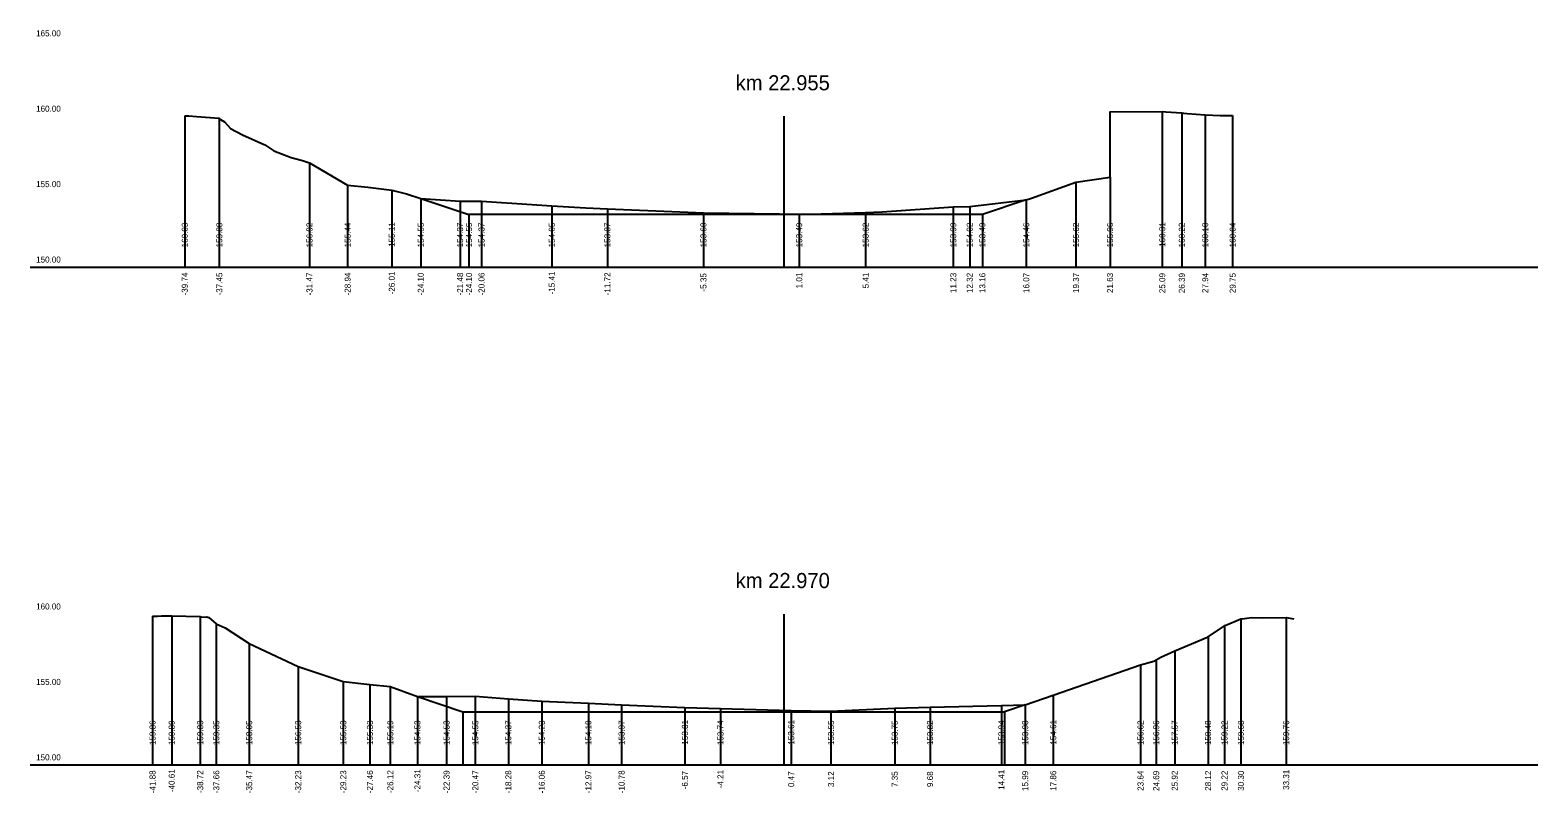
# Model space of a CAD drawing. Extents: x -582678 to -581845, y -1210354 to -1210235.
# Drawn here: x -582385.4 to -582285.4, y -1210306.7 to -1210256.2 of the extents above; entities that cross this region are included whole.
import ezdxf

# ---------------------------------------------------------------- set-up
doc = ezdxf.new("R2010")
doc.units = 0
for name, color, linetype in [('_N_osa', 7, 'Continuous'), ('_N_popis', 7, 'Continuous'), ('_N_tučná', 7, 'Continuous'), ('_S_popis', 7, 'Continuous'), ('_S_popis_oprav!', 7, 'Continuous'), ('_S_tenká', 7, 'Continuous'), ('_S_velmi_tenká', 7, 'Continuous')]:
    doc.layers.add(name, color=color, linetype=linetype)

msp = doc.modelspace()

# ---------------------------------------------------------------- linework, layer by layer
at = {"layer": '_N_osa'}
for p, q in [((-582335.45, -1210261.87), (-582335.45, -1210271.87)), ((-582335.45, -1210294.87), (-582335.45, -1210304.87))]:
    msp.add_line(p, q, dxfattribs=at)
at = {"layer": '_N_popis'}
for p, q in [((-582356.34, -1210268.38), (-582356.34, -1210271.87)), ((-582322.29, -1210268.38), (-582322.29, -1210271.87)), ((-582356.74, -1210301.35), (-582356.74, -1210304.87)), ((-582320.82, -1210301.35), (-582320.82, -1210304.87))]:
    msp.add_line(p, q, dxfattribs=at)
for points in [[(-582359.54, -1210267.32), (-582359.54, -1210271.87), (-582359.54, -1210271.87), (-582359.54, -1210271.87)], [(-582319.38, -1210267.41), (-582319.38, -1210271.87), (-582319.38, -1210271.87), (-582319.38, -1210271.87)]]:
    msp.add_lwpolyline(points, dxfattribs=at)
at = {"layer": '_N_tučná'}
for p, q in [((-582359.54, -1210267.32), (-582356.34, -1210268.38)), ((-582319.38, -1210267.41), (-582322.29, -1210268.38)), ((-582322.29, -1210268.38), (-582356.34, -1210268.38)), ((-582359.76, -1210300.34), (-582356.74, -1210301.35)), ((-582319.45, -1210300.89), (-582320.82, -1210301.35)), ((-582356.74, -1210301.35), (-582320.82, -1210301.35))]:
    msp.add_line(p, q, dxfattribs=at)
at = {"layer": '_S_tenká'}
for p, q in [((-582385.45, -1210271.87), (-582285.45, -1210271.87)), ((-582385.45, -1210304.87), (-582285.45, -1210304.87))]:
    msp.add_line(p, q, dxfattribs=at)
for points in [[(-582375.19, -1210261.84), (-582375.1, -1210261.84), (-582375.03, -1210261.85), (-582374.93, -1210261.84), (-582374.42, -1210261.88), (-582372.9, -1210261.99), (-582372.83, -1210262.08), (-582372.56, -1210262.23), (-582372.16, -1210262.68), (-582371.36, -1210263.1), (-582369.87, -1210263.77), (-582369.28, -1210264.17), (-582368.14, -1210264.6), (-582367.39, -1210264.8), (-582366.92, -1210264.95), (-582364.39, -1210266.43), (-582363.06, -1210266.58), (-582361.46, -1210266.76), (-582360.49, -1210267.01), (-582359.54, -1210267.32), (-582356.93, -1210267.5), (-582355.51, -1210267.49), (-582352.17, -1210267.71), (-582350.85, -1210267.82), (-582348.59, -1210267.94), (-582347.16, -1210268), (-582342.36, -1210268.21), (-582340.79, -1210268.27), (-582335.74, -1210268.35), (-582334.44, -1210268.38), (-582330.03, -1210268.25), (-582328.93, -1210268.2), (-582324.22, -1210267.88), (-582323.13, -1210267.85), (-582319.38, -1210267.41), (-582319.02, -1210267.29), (-582316.08, -1210266.25), (-582313.82, -1210265.91), (-582313.82, -1210261.58), (-582310.36, -1210261.56), (-582310.13, -1210261.57), (-582309.06, -1210261.65), (-582308.94, -1210261.66), (-582308.93, -1210261.66), (-582308.71, -1210261.68), (-582307.51, -1210261.77), (-582306.52, -1210261.82), (-582305.69, -1210261.83)], [(-582377.33, -1210295.01), (-582376.99, -1210295.01), (-582376.73, -1210295), (-582376.06, -1210294.98), (-582374.17, -1210295.04), (-582374.11, -1210295.05), (-582373.81, -1210295.08), (-582373.73, -1210295.06), (-582373.59, -1210295.09), (-582373.1, -1210295.52), (-582372.52, -1210295.78), (-582370.92, -1210296.82), (-582367.67, -1210298.34), (-582364.68, -1210299.34), (-582362.91, -1210299.54), (-582361.56, -1210299.68), (-582359.76, -1210300.34), (-582357.83, -1210300.33), (-582355.92, -1210300.32), (-582353.73, -1210300.5), (-582351.51, -1210300.64), (-582348.42, -1210300.77), (-582346.22, -1210300.9), (-582342.02, -1210301.06), (-582339.66, -1210301.13), (-582334.97, -1210301.26), (-582332.33, -1210301.32), (-582328.1, -1210301.12), (-582325.76, -1210301.05), (-582321.03, -1210300.93), (-582319.45, -1210300.89), (-582317.59, -1210300.25), (-582311.8, -1210298.24), (-582310.91, -1210298), (-582310.76, -1210297.91), (-582310.45, -1210297.72), (-582309.53, -1210297.3), (-582307.32, -1210296.39), (-582306.23, -1210295.65), (-582306.22, -1210295.64), (-582306.19, -1210295.63), (-582305.14, -1210295.19), (-582305.06, -1210295.18), (-582304.44, -1210295.11), (-582303.72, -1210295.13), (-582302.14, -1210295.11), (-582301.62, -1210295.18)]]:
    msp.add_lwpolyline(points, dxfattribs=at)
at = {"layer": '_S_velmi_tenká'}
for points in [[(-582375.19, -1210261.84), (-582375.19, -1210271.87), (-582375.19, -1210271.87), (-582375.19, -1210271.87)], [(-582372.9, -1210261.99), (-582372.9, -1210271.87), (-582372.9, -1210271.87), (-582372.9, -1210271.87)], [(-582310.36, -1210261.56), (-582310.36, -1210271.87), (-582310.36, -1210271.87), (-582310.36, -1210271.87)], [(-582309.06, -1210261.65), (-582309.06, -1210271.87), (-582309.06, -1210271.87), (-582309.06, -1210271.87)], [(-582307.51, -1210261.77), (-582307.51, -1210271.87), (-582307.51, -1210271.87), (-582307.51, -1210271.87)], [(-582305.69, -1210261.83), (-582305.69, -1210271.87), (-582305.69, -1210271.87), (-582305.69, -1210271.87)], [(-582366.92, -1210264.95), (-582366.92, -1210271.87), (-582366.92, -1210271.87), (-582366.92, -1210271.87)], [(-582313.82, -1210265.91), (-582313.82, -1210271.87), (-582313.82, -1210271.87), (-582313.82, -1210271.87)], [(-582364.39, -1210266.43), (-582364.39, -1210271.87), (-582364.39, -1210271.87), (-582364.39, -1210271.87)], [(-582361.46, -1210266.76), (-582361.46, -1210271.87), (-582361.46, -1210271.87), (-582361.46, -1210271.87)], [(-582316.08, -1210266.25), (-582316.08, -1210271.87), (-582316.08, -1210271.87), (-582316.08, -1210271.87)], [(-582356.93, -1210267.5), (-582356.93, -1210271.87), (-582356.93, -1210271.87), (-582356.93, -1210271.87)], [(-582355.51, -1210267.49), (-582355.51, -1210271.87), (-582355.51, -1210271.87), (-582355.51, -1210271.87)], [(-582350.85, -1210267.82), (-582350.85, -1210271.87), (-582350.85, -1210271.87), (-582350.85, -1210271.87)], [(-582347.16, -1210268), (-582347.16, -1210271.87), (-582347.16, -1210271.87), (-582347.16, -1210271.87)], [(-582324.22, -1210267.88), (-582324.22, -1210271.87), (-582324.22, -1210271.87), (-582324.22, -1210271.87)], [(-582323.13, -1210267.85), (-582323.13, -1210271.87), (-582323.13, -1210271.87), (-582323.13, -1210271.87)], [(-582340.79, -1210268.27), (-582340.79, -1210271.87), (-582340.79, -1210271.87), (-582340.79, -1210271.87)], [(-582334.44, -1210268.38), (-582334.44, -1210271.87), (-582334.44, -1210271.87), (-582334.44, -1210271.87)], [(-582330.03, -1210268.25), (-582330.03, -1210271.87), (-582330.03, -1210271.87), (-582330.03, -1210271.87)], [(-582376.06, -1210294.98), (-582376.06, -1210304.87), (-582376.06, -1210304.87), (-582376.06, -1210304.87)], [(-582377.33, -1210295.01), (-582377.33, -1210304.87), (-582377.33, -1210304.87), (-582377.33, -1210304.87)], [(-582374.17, -1210295.04), (-582374.17, -1210304.87), (-582374.17, -1210304.87), (-582374.17, -1210304.87)], [(-582373.1, -1210295.52), (-582373.1, -1210304.87), (-582373.1, -1210304.87), (-582373.1, -1210304.87)], [(-582306.23, -1210295.65), (-582306.23, -1210304.87), (-582306.23, -1210304.87), (-582306.23, -1210304.87)], [(-582305.14, -1210295.19), (-582305.14, -1210304.87), (-582305.14, -1210304.87), (-582305.14, -1210304.87)], [(-582302.14, -1210295.11), (-582302.14, -1210304.87), (-582302.14, -1210304.87), (-582302.14, -1210304.87)], [(-582370.92, -1210296.82), (-582370.92, -1210304.87), (-582370.92, -1210304.87), (-582370.92, -1210304.87)], [(-582307.32, -1210296.39), (-582307.32, -1210304.87), (-582307.32, -1210304.87), (-582307.32, -1210304.87)], [(-582310.76, -1210297.91), (-582310.76, -1210304.87), (-582310.76, -1210304.87), (-582310.76, -1210304.87)], [(-582309.53, -1210297.3), (-582309.53, -1210304.87), (-582309.53, -1210304.87), (-582309.53, -1210304.87)], [(-582367.67, -1210298.34), (-582367.67, -1210304.87), (-582367.67, -1210304.87), (-582367.67, -1210304.87)], [(-582311.8, -1210298.24), (-582311.8, -1210304.87), (-582311.8, -1210304.87), (-582311.8, -1210304.87)], [(-582364.68, -1210299.34), (-582364.68, -1210304.87), (-582364.68, -1210304.87), (-582364.68, -1210304.87)], [(-582362.91, -1210299.54), (-582362.91, -1210304.87), (-582362.91, -1210304.87), (-582362.91, -1210304.87)], [(-582361.56, -1210299.68), (-582361.56, -1210304.87), (-582361.56, -1210304.87), (-582361.56, -1210304.87)], [(-582359.76, -1210300.34), (-582359.76, -1210304.87), (-582359.76, -1210304.87), (-582359.76, -1210304.87)], [(-582357.83, -1210300.33), (-582357.83, -1210304.87), (-582357.83, -1210304.87), (-582357.83, -1210304.87)], [(-582355.92, -1210300.32), (-582355.92, -1210304.87), (-582355.92, -1210304.87), (-582355.92, -1210304.87)], [(-582353.73, -1210300.5), (-582353.73, -1210304.87), (-582353.73, -1210304.87), (-582353.73, -1210304.87)], [(-582351.51, -1210300.64), (-582351.51, -1210304.87), (-582351.51, -1210304.87), (-582351.51, -1210304.87)], [(-582348.42, -1210300.77), (-582348.42, -1210304.87), (-582348.42, -1210304.87), (-582348.42, -1210304.87)], [(-582346.22, -1210300.9), (-582346.22, -1210304.87), (-582346.22, -1210304.87), (-582346.22, -1210304.87)], [(-582321.03, -1210300.93), (-582321.03, -1210304.87), (-582321.03, -1210304.87), (-582321.03, -1210304.87)], [(-582319.45, -1210300.89), (-582319.45, -1210304.87), (-582319.45, -1210304.87), (-582319.45, -1210304.87)], [(-582317.59, -1210300.25), (-582317.59, -1210304.87), (-582317.59, -1210304.87), (-582317.59, -1210304.87)], [(-582342.02, -1210301.06), (-582342.02, -1210304.87), (-582342.02, -1210304.87), (-582342.02, -1210304.87)], [(-582339.66, -1210301.13), (-582339.66, -1210304.87), (-582339.66, -1210304.87), (-582339.66, -1210304.87)], [(-582334.97, -1210301.26), (-582334.97, -1210304.87), (-582334.97, -1210304.87), (-582334.97, -1210304.87)], [(-582332.33, -1210301.32), (-582332.33, -1210304.87), (-582332.33, -1210304.87), (-582332.33, -1210304.87)], [(-582328.1, -1210301.12), (-582328.1, -1210304.87), (-582328.1, -1210304.87), (-582328.1, -1210304.87)], [(-582325.76, -1210301.05), (-582325.76, -1210304.87), (-582325.76, -1210304.87), (-582325.76, -1210304.87)]]:
    msp.add_lwpolyline(points, dxfattribs=at)

# ---------------------------------------------------------------- texts
at = {"layer": '_N_popis'}
for s, p in [('154.55', (-582359.34, -1210270.56)), ('154.55', (-582356.14, -1210270.56)), ('153.49', (-582322.09, -1210270.56)), ('154.46', (-582319.18, -1210270.56)), ('-24.10', (-582359.34, -1210273.75)), ('-24.10', (-582356.14, -1210273.75)), ('13.16', (-582322.09, -1210273.59)), ('16.07', (-582319.18, -1210273.59))]:
    msp.add_text(s, height=0.4, rotation=90, dxfattribs=at).set_placement(p)
at = {"layer": '_S_popis'}
for s, p in [('165.00', (-582385.05, -1210256.57)), ('160.00', (-582385.05, -1210261.57)), ('155.00', (-582385.05, -1210266.57)), ('150.00', (-582385.05, -1210271.57)), ('160.00', (-582385.05, -1210294.57)), ('155.00', (-582385.05, -1210299.57)), ('150.00', (-582385.05, -1210304.57))]:
    msp.add_text(s, height=0.4, dxfattribs=at).set_placement(p)
for s, p in [('160.03', (-582374.99, -1210270.56)), ('159.88', (-582372.7, -1210270.56)), ('156.92', (-582366.72, -1210270.56)), ('155.44', (-582364.19, -1210270.56)), ('155.11', (-582361.26, -1210270.53)), ('154.37', (-582356.73, -1210270.56)), ('154.37', (-582355.31, -1210270.56)), ('154.05', (-582350.65, -1210270.56)), ('153.87', (-582346.96, -1210270.56)), ('153.60', (-582340.59, -1210270.56)), ('153.49', (-582334.24, -1210270.56)), ('153.62', (-582329.83, -1210270.56)), ('153.99', (-582324.02, -1210270.56)), ('154.02', (-582322.93, -1210270.56)), ('155.62', (-582315.88, -1210270.56)), ('155.96', (-582313.62, -1210270.56)), ('160.31', (-582310.16, -1210270.53)), ('160.22', (-582308.86, -1210270.56)), ('160.10', (-582307.31, -1210270.56)), ('160.04', (-582305.49, -1210270.56)), ('-39.74', (-582374.99, -1210273.75)), ('-37.45', (-582372.7, -1210273.75)), ('-31.47', (-582366.72, -1210273.75)), ('-28.94', (-582364.19, -1210273.75)), ('-26.01', (-582361.26, -1210273.68)), ('-21.48', (-582356.73, -1210273.75)), ('-20.06', (-582355.31, -1210273.75)), ('-15.41', (-582350.65, -1210273.68)), ('-11.72', (-582346.96, -1210273.74)), ('-5.35', (-582340.59, -1210273.49)), ('1.01', (-582334.24, -1210273.28)), ('5.41', (-582329.83, -1210273.28)), ('11.23', (-582324.02, -1210273.59)), ('12.32', (-582322.93, -1210273.59)), ('19.37', (-582315.88, -1210273.59)), ('21.63', (-582313.62, -1210273.59)), ('25.09', (-582310.16, -1210273.6)), ('26.39', (-582308.86, -1210273.6)), ('27.94', (-582307.31, -1210273.59)), ('29.75', (-582305.49, -1210273.6)), ('159.86', (-582377.13, -1210303.56)), ('159.89', (-582375.86, -1210303.56)), ('159.83', (-582373.97, -1210303.56)), ('159.35', (-582372.9, -1210303.56)), ('158.05', (-582370.72, -1210303.56)), ('156.53', (-582367.47, -1210303.56)), ('155.53', (-582364.48, -1210303.56)), ('155.33', (-582362.71, -1210303.56)), ('155.19', (-582361.36, -1210303.56)), ('154.53', (-582359.56, -1210303.56)), ('154.53', (-582357.63, -1210303.56)), ('154.55', (-582355.72, -1210303.56)), ('154.37', (-582353.53, -1210303.56)), ('154.23', (-582351.31, -1210303.56)), ('154.10', (-582348.22, -1210303.56)), ('153.97', (-582346.02, -1210303.56)), ('153.81', (-582341.82, -1210303.53)), ('153.74', (-582339.46, -1210303.56)), ('153.61', (-582334.77, -1210303.53)), ('153.55', (-582332.13, -1210303.56)), ('153.75', (-582327.9, -1210303.56)), ('153.82', (-582325.56, -1210303.56)), ('153.94', (-582320.83, -1210303.56)), ('153.98', (-582319.25, -1210303.56)), ('154.61', (-582317.39, -1210303.53)), ('156.62', (-582311.6, -1210303.56)), ('156.96', (-582310.56, -1210303.56)), ('157.57', (-582309.33, -1210303.56)), ('158.48', (-582307.12, -1210303.56)), ('159.22', (-582306.03, -1210303.56)), ('159.68', (-582304.94, -1210303.56)), ('159.76', (-582301.94, -1210303.56)), ('-41.88', (-582377.13, -1210306.75)), ('-40.61', (-582375.86, -1210306.68)), ('-38.72', (-582373.97, -1210306.74)), ('-37.66', (-582372.9, -1210306.75)), ('-35.47', (-582370.72, -1210306.75)), ('-32.23', (-582367.47, -1210306.75)), ('-29.23', (-582364.48, -1210306.75)), ('-27.46', (-582362.71, -1210306.75)), ('-26.12', (-582361.36, -1210306.74)), ('-24.31', (-582359.56, -1210306.68)), ('-22.39', (-582357.63, -1210306.75)), ('-20.47', (-582355.72, -1210306.75)), ('-18.28', (-582353.53, -1210306.75)), ('-16.06', (-582351.31, -1210306.75)), ('-12.97', (-582348.22, -1210306.75)), ('-10.78', (-582346.02, -1210306.75)), ('-6.57', (-582341.82, -1210306.49)), ('-4.21', (-582339.46, -1210306.43)), ('0.47', (-582334.77, -1210306.34)), ('3.12', (-582332.13, -1210306.34)), ('7.35', (-582327.9, -1210306.34)), ('9.68', (-582325.56, -1210306.34)), ('14.41', (-582320.83, -1210306.53)), ('15.99', (-582319.25, -1210306.6)), ('17.86', (-582317.39, -1210306.59)), ('23.64', (-582311.6, -1210306.59)), ('24.69', (-582310.56, -1210306.6)), ('25.92', (-582309.33, -1210306.59)), ('28.12', (-582307.12, -1210306.59)), ('29.22', (-582306.03, -1210306.59)), ('30.30', (-582304.94, -1210306.59)), ('33.31', (-582301.94, -1210306.53))]:
    msp.add_text(s, height=0.4, rotation=90, dxfattribs=at).set_placement(p)
at = {"layer": '_S_popis_oprav!'}
for s, p in [('km 22.955', (-582338.65, -1210260.15)), ('km 22.970', (-582338.65, -1210293.15))]:
    msp.add_text(s, height=1, dxfattribs=at).set_placement(p)

doc.saveas('drawing.dxf')
